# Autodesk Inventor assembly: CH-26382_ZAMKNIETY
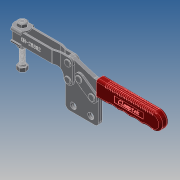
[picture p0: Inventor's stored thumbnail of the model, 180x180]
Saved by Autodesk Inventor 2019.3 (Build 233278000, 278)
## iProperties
Company: Î¢ÈíÖÐ¹ú
Created: 2012-09
Part Number: CH-26382_ZAMKNIETY
Material: Ogólny
Description: STEP AP203
Document SubType Name: Assembly
Designer: CADENGINEERING4
Stock Number: DOCISKI POZIOME
Sending System: SolidWorks 2010
Preprocessor: SwSTEP 2.0
Title: CH-26382.STEP
Author: Î¢ÈíÓÃ»§
Revision Number: ÈÎºÎ
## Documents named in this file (10)
- E:\STRONA\Horizontal toggle clamp\CH-26382\CH-26382_ZAMKNIETY.iam
- E:\STRONA\Horizontal toggle clamp\CH-26382\M8.ipt
- E:\STRONA\Horizontal toggle clamp\CH-26382\01.ipt
- E:\STRONA\Horizontal toggle clamp\CH-26382\25382-04.ipt
- E:\STRONA\Horizontal toggle clamp\CH-26382\25382-05.ipt
- E:\STRONA\Horizontal toggle clamp\CH-26382\26382-02.ipt
- E:\STRONA\Horizontal toggle clamp\CH-26382\26382-01.ipt
- E:\STRONA\Horizontal toggle clamp\CH-26382\086512.ipt
- E:\STRONA\Horizontal toggle clamp\CH-26382\FW380.ipt
- E:\STRONA\Horizontal toggle clamp\CH-26382\25382-03.ipt
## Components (15 placed, 15 different names)
1. M8_1 — Równoległe:3, Zestawiające:6, Zestawiające:9
2. 01_2 — Zestawiające:1, Zestawiające:2, Zestawiające:8
3. M8_3 — Zestawiające:12, Zestawiające:13
4. 25382-04_4 — Zestawiające:15, Zestawiające:18, Zestawiające:19, Zestawiające:20, Zestawiające:21, Zestawiające:22, Zestawiające:25
5. 25382-05_5 — Zestawiające:31, Zestawiające:32
6. 25382-05_6 — Zestawiające:25, Zestawiające:33, Zestawiające:34
7. 26382-02_7 — Równoległe:1, Zestawiające:7, Zestawiające:11, Zestawiające:14, Zestawiające:26, Zestawiające:27, Zestawiające:28, Zestawiające:29, Zestawiające:30, Zestawiające:31, Zestawiające:32
8. 25382-05_8 — Zestawiające:20, Zestawiające:21
9. 26382-01_9 — Zestawiające:15, Zestawiające:16, Zestawiające:17, Zestawiające:18, Zestawiające:26, Zestawiające:27, Przejściowe:1
10. 25382-04_10 — Zestawiające:16, Zestawiające:17, Zestawiające:19, Zestawiające:33
11. 086512_11 — Równoległe:3, Zestawiające:5, Zestawiające:9, Zestawiające:10, Zestawiające:12, Zestawiające:14
12. FW380_12 — Równoległe:1, Równoległe:2, Zestawiające:5, Zestawiające:6, Zestawiające:7
13. FW380_13 — Równoległe:2, Zestawiające:10, Zestawiające:11, Zestawiające:13
14. 25382-03_14 — Zestawiające:1, Zestawiające:2, Zestawiające:8, Zestawiające:22, Zestawiające:30, Zestawiające:34, Przejściowe:1
15. 25382-05_15 — Zestawiające:28, Zestawiające:29
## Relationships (34: Mate 30, Flush 3, Transitional 1)
- Zestawiające:1 [Mate]: 01_2 ↔ 25382-03_14
- Zestawiające:2 [Mate]: 01_2 ↔ 25382-03_14
- Równoległe:1 [Flush]: 26382-02_7 ↔ FW380_12
- Równoległe:2 [Flush]: FW380_12 ↔ FW380_13
- Równoległe:3 [Flush]: M8_1 ↔ 086512_11
- Zestawiające:5 [Mate]: 086512_11 ↔ FW380_12
- Zestawiające:6 [Mate]: M8_1 ↔ FW380_12
- Zestawiające:7 [Mate]: 26382-02_7 ↔ FW380_12
- Zestawiające:8 [Mate]: 01_2 ↔ 25382-03_14
- Zestawiające:9 [Mate]: M8_1 ↔ 086512_11
- Zestawiające:10 [Mate]: 086512_11 ↔ FW380_13
- Zestawiające:11 [Mate]: 26382-02_7 ↔ FW380_13
- Zestawiające:12 [Mate]: M8_3 ↔ 086512_11
- Zestawiające:13 [Mate]: M8_3 ↔ FW380_13
- Zestawiające:14 [Mate]: 26382-02_7 ↔ 086512_11
- Zestawiające:15 [Mate]: 25382-04_4 ↔ 26382-01_9
- Zestawiające:16 [Mate]: 26382-01_9 ↔ 25382-04_10
- Zestawiające:17 [Mate]: 26382-01_9 ↔ 25382-04_10
- Zestawiające:18 [Mate]: 25382-04_4 ↔ 26382-01_9
- Zestawiające:19 [Mate]: 25382-04_4 ↔ 25382-04_10
- Zestawiające:20 [Mate]: 25382-04_4 ↔ 25382-05_8
- Zestawiające:21 [Mate]: 25382-04_4 ↔ 25382-05_8
- Zestawiające:22 [Mate]: 25382-04_4 ↔ 25382-03_14
- Zestawiające:25 [Mate]: 25382-04_4 ↔ 25382-05_6
- Zestawiające:26 [Mate]: 26382-02_7 ↔ 26382-01_9
- Zestawiające:27 [Mate]: 26382-02_7 ↔ 26382-01_9
- Zestawiające:28 [Mate]: 26382-02_7 ↔ 25382-05_15
- Zestawiające:29 [Mate]: 26382-02_7 ↔ 25382-05_15
- Zestawiające:30 [Mate]: 26382-02_7 ↔ 25382-03_14
- Zestawiające:31 [Mate]: 25382-05_5 ↔ 26382-02_7
- Zestawiające:32 [Mate]: 25382-05_5 ↔ 26382-02_7
- Zestawiające:33 [Mate]: 25382-05_6 ↔ 25382-04_10
- Zestawiające:34 [Mate]: 25382-05_6 ↔ 25382-03_14
- Przejściowe:1 [Transitional]: 26382-01_9 ↔ 25382-03_14
